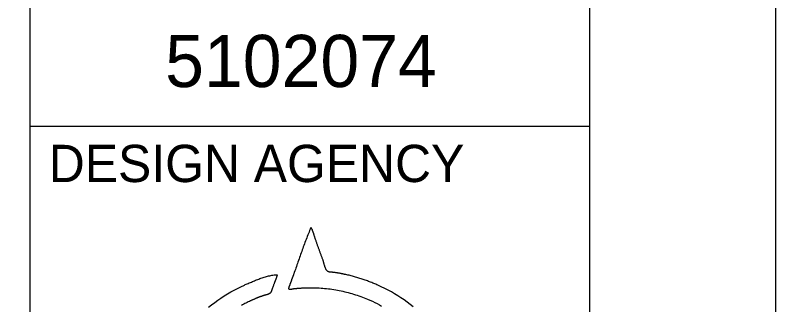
# Model space of a CAD drawing. Extents: x 0 to 34, y 0 to 22.
# Drawn here: x 31.96 to 34, y 4.521 to 5.298 of the extents above; entities that cross this region are included whole.
import ezdxf

# ---------------------------------------------------------------- set-up
doc = ezdxf.new("R2010")
doc.units = 0
for name, color, linetype in [('SH_Border', 7, 'Continuous'), ('SH_Cut_Line', 7, 'Continuous'), ('SH_Data', 7, 'Continuous'), ('SH_Text', 7, 'Continuous')]:
    doc.layers.add(name, color=color, linetype=linetype)

msp = doc.modelspace()

# ---------------------------------------------------------------- linework, layer by layer
at = {"layer": 'SH_Border'}
for p, q in [((32, 0.5), (32, 21.5)), ((32, 5), (33.5, 5))]:
    msp.add_line(p, q, dxfattribs=at)
msp.add_lwpolyline([(1.5, 21.5), (33.5, 21.5), (33.5, 0.5), (1.5, 0.5)], close=True, dxfattribs=at)
at = {"layer": 'SH_Cut_Line'}
msp.add_lwpolyline([(0, 0), (34, 0), (34, 22), (0, 22)], close=True, dxfattribs=at)
at = {"layer": 'SH_Text'}
for points in [[(32.7532, 4.7277), (32.7515, 4.7238), (32.7498, 4.7199), (32.7481, 4.716), (32.7466, 4.712), (32.745, 4.708), (32.7434, 4.7041), (32.7418, 4.7001), (32.7403, 4.6961), (32.7387, 4.6921), (32.7372, 4.6881), (32.7357, 4.6841), (32.7342, 4.6801), (32.7328, 4.676), (32.7313, 4.672), (32.7298, 4.668), (32.7284, 4.6639), (32.7271, 4.6599), (32.7256, 4.6558), (32.7241, 4.6518), (32.7227, 4.6478), (32.7214, 4.6436), (32.7199, 4.6396), (32.7184, 4.6355), (32.7171, 4.6315), (32.7157, 4.6275), (32.7142, 4.6235), (32.7129, 4.6194), (32.7114, 4.6154), (32.71, 4.6114), (32.7085, 4.6074), (32.707, 4.6035)], [(32.7656, 4.6959), (32.7652, 4.6969), (32.7649, 4.6978), (32.7646, 4.6988), (32.7643, 4.6998), (32.764, 4.7009), (32.7637, 4.702), (32.7633, 4.7031), (32.7631, 4.7041), (32.7627, 4.7051), (32.7623, 4.7063), (32.7621, 4.7074), (32.7617, 4.7085), (32.7614, 4.7096), (32.761, 4.7107), (32.7606, 4.7118), (32.7603, 4.7129), (32.7599, 4.714), (32.7595, 4.7151), (32.7592, 4.7161), (32.7587, 4.7172), (32.7583, 4.7182), (32.7578, 4.7193), (32.7575, 4.7203), (32.757, 4.7214), (32.7565, 4.7223), (32.756, 4.7233), (32.7555, 4.7242), (32.7549, 4.7251), (32.7545, 4.726), (32.7538, 4.7268), (32.7532, 4.7277)], [(32.7856, 4.6404), (32.785, 4.6422), (32.7844, 4.644), (32.7837, 4.6457), (32.7831, 4.6475), (32.7823, 4.6493), (32.7817, 4.6512), (32.781, 4.6529), (32.7804, 4.6547), (32.7797, 4.6565), (32.7791, 4.6582), (32.7783, 4.66), (32.7777, 4.6618), (32.777, 4.6637), (32.7764, 4.6654), (32.7758, 4.6672), (32.7751, 4.669), (32.7745, 4.6708), (32.7739, 4.6725), (32.7731, 4.6743), (32.7725, 4.6761), (32.7719, 4.678), (32.7712, 4.6797), (32.7706, 4.6815), (32.77, 4.6833), (32.7694, 4.6851), (32.7686, 4.6869), (32.768, 4.6886), (32.7674, 4.6904), (32.7668, 4.6923), (32.7662, 4.6941), (32.7656, 4.6959)], [(32.7979, 4.6106), (32.7973, 4.6112), (32.7966, 4.6118), (32.796, 4.6124), (32.7954, 4.6131), (32.7949, 4.6138), (32.7943, 4.6147), (32.7939, 4.6156), (32.7934, 4.6165), (32.7929, 4.6175), (32.7925, 4.6186), (32.792, 4.6195), (32.7917, 4.6206), (32.7913, 4.6217), (32.7908, 4.6228), (32.7905, 4.6239), (32.7901, 4.6251), (32.7899, 4.6262), (32.7895, 4.6274), (32.7891, 4.6285), (32.7889, 4.6296), (32.7885, 4.6308), (32.7882, 4.6319), (32.7879, 4.633), (32.7877, 4.6341), (32.7873, 4.635), (32.7871, 4.636), (32.7868, 4.637), (32.7865, 4.638), (32.7862, 4.6388), (32.786, 4.6396), (32.7856, 4.6404)], [(32.8139, 4.6075), (32.8134, 4.6075), (32.8129, 4.6076), (32.8124, 4.6076), (32.8119, 4.6076), (32.8114, 4.6078), (32.8108, 4.6078), (32.8103, 4.6078), (32.8097, 4.6078), (32.8093, 4.6079), (32.8086, 4.6079), (32.808, 4.6079), (32.8076, 4.6079), (32.807, 4.608), (32.8063, 4.608), (32.8059, 4.6081), (32.8053, 4.6081), (32.8046, 4.6082), (32.8042, 4.6082), (32.8036, 4.6084), (32.8031, 4.6085), (32.8025, 4.6086), (32.802, 4.6087), (32.8015, 4.6089), (32.8009, 4.609), (32.8004, 4.6092), (32.7999, 4.6093), (32.7996, 4.6096), (32.7991, 4.6098), (32.7986, 4.6101), (32.7982, 4.6103), (32.7979, 4.6106)], [(32.5747, 4.5736), (32.5772, 4.5747), (32.5799, 4.5759), (32.5825, 4.577), (32.5852, 4.5782), (32.5879, 4.5794), (32.5907, 4.5806), (32.5934, 4.5818), (32.5962, 4.5829), (32.599, 4.5841), (32.6018, 4.5853), (32.6047, 4.5864), (32.6075, 4.5876), (32.6104, 4.5887), (32.6133, 4.5898), (32.6162, 4.5909), (32.6192, 4.5919), (32.6221, 4.593), (32.6251, 4.5938), (32.628, 4.5948), (32.6309, 4.5956), (32.6338, 4.5965), (32.6369, 4.5973), (32.6398, 4.5981), (32.6427, 4.5987), (32.6456, 4.5993), (32.6485, 4.5998), (32.6514, 4.6002), (32.6543, 4.6007), (32.6572, 4.601), (32.6601, 4.6012), (32.6629, 4.6015)], [(32.6629, 4.6015), (32.6626, 4.6002), (32.6623, 4.5992), (32.6619, 4.5979), (32.6616, 4.5969), (32.6612, 4.5958), (32.6609, 4.5945), (32.6605, 4.5935), (32.6601, 4.5922), (32.6596, 4.5912), (32.6593, 4.5901), (32.6589, 4.5888), (32.6584, 4.5878), (32.6581, 4.5867), (32.6576, 4.5856), (32.6572, 4.5844), (32.6567, 4.5833), (32.6564, 4.5822), (32.6559, 4.5811), (32.6555, 4.5799), (32.655, 4.5788), (32.6546, 4.5777), (32.6542, 4.5766), (32.6537, 4.5754), (32.6532, 4.5743), (32.6529, 4.5732), (32.6524, 4.5721), (32.652, 4.571), (32.6515, 4.5698), (32.6512, 4.5687), (32.6507, 4.5676), (32.6503, 4.5665)], [(32.707, 4.6035), (32.7067, 4.6025), (32.7063, 4.6016), (32.7061, 4.6006), (32.7057, 4.5996), (32.7054, 4.5987), (32.705, 4.5977), (32.7046, 4.5967), (32.7043, 4.5958), (32.7039, 4.5948), (32.7037, 4.5938), (32.7033, 4.5928), (32.7029, 4.592), (32.7026, 4.591), (32.7022, 4.5901), (32.7018, 4.5891), (32.7015, 4.5881), (32.7011, 4.5872), (32.7007, 4.5862), (32.7005, 4.5852), (32.7001, 4.5842), (32.6998, 4.5833), (32.6994, 4.5823), (32.699, 4.5813), (32.6987, 4.5804), (32.6983, 4.5795), (32.698, 4.5785), (32.6976, 4.5776), (32.6972, 4.5766), (32.6969, 4.5756), (32.6965, 4.5747), (32.6963, 4.5737)], [(32.8436, 4.6024), (32.8426, 4.6027), (32.8417, 4.6028), (32.8408, 4.603), (32.8398, 4.6033), (32.8388, 4.6034), (32.8379, 4.6036), (32.8369, 4.6038), (32.8359, 4.604), (32.835, 4.6041), (32.8341, 4.6044), (32.8331, 4.6045), (32.8322, 4.6047), (32.8312, 4.6049), (32.8302, 4.6051), (32.8293, 4.6052), (32.8283, 4.6055), (32.8273, 4.6056), (32.8263, 4.6057), (32.8254, 4.6059), (32.8244, 4.6061), (32.8234, 4.6062), (32.8225, 4.6063), (32.8215, 4.6065), (32.8205, 4.6067), (32.8196, 4.6068), (32.8186, 4.6069), (32.8177, 4.607), (32.8168, 4.6072), (32.8158, 4.6073), (32.8148, 4.6074), (32.8139, 4.6075)], [(32.9329, 4.5732), (32.9301, 4.5744), (32.9273, 4.5756), (32.9246, 4.5768), (32.9216, 4.5781), (32.9189, 4.5791), (32.9161, 4.5802), (32.9133, 4.5815), (32.9104, 4.5825), (32.9076, 4.5835), (32.9048, 4.5846), (32.9019, 4.5857), (32.8991, 4.5867), (32.8962, 4.5878), (32.8933, 4.5887), (32.8905, 4.5897), (32.8876, 4.5907), (32.8847, 4.5915), (32.8818, 4.5925), (32.8788, 4.5933), (32.8759, 4.5943), (32.873, 4.5952), (32.8701, 4.596), (32.8672, 4.5967), (32.8643, 4.5976), (32.8614, 4.5983), (32.8584, 4.599), (32.8554, 4.5998), (32.8525, 4.6005), (32.8495, 4.6012), (32.8466, 4.6018), (32.8436, 4.6024)], [(32.4788, 4.5143), (32.4868, 4.5207), (32.495, 4.5269), (32.5034, 4.533), (32.5119, 4.5388), (32.5205, 4.5445), (32.5292, 4.5498), (32.538, 4.555), (32.547, 4.56), (32.5561, 4.5647), (32.5653, 4.5693), (32.5747, 4.5736)], [(32.6963, 4.5737), (32.6961, 4.5735), (32.696, 4.5732), (32.6959, 4.573), (32.6958, 4.5727), (32.6957, 4.5724), (32.6955, 4.5721), (32.6954, 4.5718), (32.6952, 4.5714), (32.695, 4.571), (32.6949, 4.5707), (32.6947, 4.5703), (32.6946, 4.5699), (32.6944, 4.5696), (32.6942, 4.5691), (32.6941, 4.5687), (32.694, 4.5684), (32.6938, 4.568), (32.6937, 4.5675), (32.6936, 4.5671), (32.6935, 4.5668), (32.6935, 4.5664), (32.6933, 4.5661), (32.6933, 4.5657), (32.6932, 4.5653), (32.6932, 4.565), (32.6932, 4.5647), (32.6933, 4.5644), (32.6933, 4.5641), (32.6935, 4.5639), (32.6936, 4.5636), (32.6937, 4.5634)], [(33.0272, 4.5154), (33.0194, 4.5217), (33.0112, 4.5277), (33.0031, 4.5337), (32.9947, 4.5394), (32.9863, 4.545), (32.9777, 4.5503), (32.9689, 4.5553), (32.9601, 4.5601), (32.9511, 4.5647), (32.942, 4.5691), (32.9329, 4.5732)], [(32.6438, 4.5519), (32.6434, 4.5515), (32.6429, 4.5511), (32.6424, 4.5508), (32.6421, 4.5505), (32.6415, 4.5502), (32.641, 4.5499), (32.6405, 4.5497), (32.6399, 4.5493), (32.6393, 4.5491), (32.6387, 4.5488), (32.6381, 4.5487), (32.6375, 4.5485), (32.6369, 4.5482), (32.6362, 4.5481), (32.6356, 4.5479), (32.635, 4.5476), (32.6343, 4.5475), (32.6337, 4.5474), (32.6331, 4.5471), (32.6324, 4.547), (32.6318, 4.5469), (32.6312, 4.5467), (32.6305, 4.5465), (32.6299, 4.5464), (32.6293, 4.5463), (32.6287, 4.5461), (32.6281, 4.5459), (32.6275, 4.5458), (32.627, 4.5456), (32.6264, 4.5454), (32.6259, 4.5453)], [(32.6503, 4.5665), (32.6501, 4.5661), (32.6499, 4.5656), (32.6498, 4.5652), (32.6496, 4.5647), (32.6495, 4.5642), (32.6493, 4.5638), (32.6492, 4.5631), (32.649, 4.5627), (32.6489, 4.5622), (32.6487, 4.5617), (32.6485, 4.5611), (32.6484, 4.5606), (32.6481, 4.5601), (32.648, 4.5595), (32.6478, 4.559), (32.6476, 4.5585), (32.6474, 4.5579), (32.6473, 4.5574), (32.647, 4.557), (32.6468, 4.5565), (32.6466, 4.556), (32.6463, 4.5555), (32.6461, 4.555), (32.6458, 4.5545), (32.6456, 4.5542), (32.6453, 4.5537), (32.6451, 4.5533), (32.6447, 4.553), (32.6445, 4.5525), (32.6441, 4.5521), (32.6438, 4.5519)], [(32.6937, 4.5634), (32.694, 4.5633), (32.6942, 4.563), (32.6946, 4.5629), (32.6949, 4.5628), (32.6954, 4.5627), (32.6958, 4.5627), (32.6963, 4.5625), (32.6967, 4.5625), (32.6973, 4.5625), (32.6978, 4.5625), (32.6984, 4.5625), (32.699, 4.5627), (32.6997, 4.5627), (32.7003, 4.5628), (32.7009, 4.5629), (32.7015, 4.563), (32.7021, 4.563), (32.7027, 4.5631), (32.7033, 4.5633), (32.7039, 4.5634), (32.7045, 4.5635), (32.705, 4.5636), (32.7056, 4.5638), (32.7062, 4.5639), (32.7067, 4.564), (32.7072, 4.5641), (32.7077, 4.5641), (32.708, 4.5642), (32.7085, 4.5644), (32.7087, 4.5644), (32.7091, 4.5644)], [(32.7091, 4.5644), (32.7106, 4.5645), (32.7121, 4.5646), (32.7136, 4.5647), (32.7151, 4.5648), (32.7166, 4.565), (32.7181, 4.5651), (32.7195, 4.5652), (32.721, 4.5653), (32.7226, 4.5654), (32.724, 4.5656), (32.7255, 4.5657), (32.7269, 4.5657), (32.7285, 4.5658), (32.73, 4.5659), (32.7314, 4.5659), (32.7329, 4.5661), (32.7344, 4.5661), (32.7359, 4.5662), (32.7374, 4.5662), (32.7388, 4.5663), (32.7404, 4.5663), (32.7418, 4.5663), (32.7433, 4.5664), (32.7449, 4.5664), (32.7463, 4.5664), (32.7478, 4.5664), (32.7494, 4.5665), (32.7508, 4.5665), (32.7523, 4.5665), (32.7538, 4.5665), (32.7553, 4.5665)], [(32.7553, 4.5665), (32.7603, 4.5665), (32.7652, 4.5664), (32.7702, 4.5662), (32.7752, 4.5659), (32.7802, 4.5657), (32.785, 4.5653), (32.79, 4.5648), (32.7949, 4.5644), (32.7999, 4.5638), (32.8048, 4.5631), (32.8097, 4.5624), (32.8146, 4.5617), (32.8196, 4.5608), (32.8244, 4.56), (32.8293, 4.559), (32.8341, 4.5581), (32.839, 4.557), (32.8438, 4.5558), (32.8487, 4.5547), (32.8534, 4.5533), (32.8582, 4.552), (32.863, 4.5507), (32.8678, 4.5492), (32.8725, 4.5477), (32.8773, 4.5462), (32.882, 4.5446), (32.8866, 4.5429), (32.8913, 4.5412), (32.8959, 4.5394), (32.9005, 4.5376), (32.9052, 4.5357)], [(32.591, 4.5313), (32.588, 4.5299), (32.585, 4.5284), (32.5819, 4.5269), (32.5789, 4.5254), (32.5759, 4.5239), (32.5728, 4.5223), (32.5698, 4.5207), (32.5669, 4.5191)], [(32.6259, 4.5453), (32.6248, 4.545), (32.6236, 4.5445), (32.6225, 4.5441), (32.6213, 4.5437), (32.6202, 4.5433), (32.6192, 4.5429), (32.6179, 4.5425), (32.6168, 4.5421), (32.6156, 4.5417), (32.6145, 4.5412), (32.6135, 4.5407), (32.6122, 4.5404), (32.6111, 4.5399), (32.6101, 4.5394), (32.6088, 4.539), (32.6078, 4.5385), (32.6067, 4.538), (32.6055, 4.5376), (32.6044, 4.5372), (32.6033, 4.5367), (32.6022, 4.5362), (32.601, 4.5357), (32.5999, 4.5353), (32.5988, 4.5348), (32.5977, 4.5343), (32.5966, 4.5338), (32.5955, 4.5333), (32.5944, 4.5328), (32.5932, 4.5324), (32.5921, 4.5317), (32.591, 4.5313)], [(32.9052, 4.5357), (32.9116, 4.533), (32.9179, 4.5302), (32.9242, 4.5271), (32.9305, 4.5241), (32.9367, 4.5208), (32.9427, 4.5174)]]:
    msp.add_lwpolyline(points, dxfattribs=at)

# ---------------------------------------------------------------- texts
at = {"layer": 'SH_Data'}
for s, height, p in [('5102074', 0.14, (32.3621, 5.105)), ('DESIGN AGENCY', 0.1, (32.05, 4.85))]:
    msp.add_text(s, height=height, dxfattribs=at).set_placement(p)

doc.saveas('drawing.dxf')
